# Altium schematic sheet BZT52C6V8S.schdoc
size 127 x 101 mm
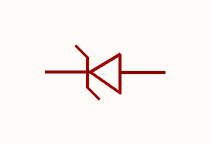
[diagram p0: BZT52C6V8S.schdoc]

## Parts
ZD?  bzt52c6v8s_c22613  [SOD-323_L1.8-W1.3-LS2.5-RD]  (value not drawn)

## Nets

Not connected (* = marked no-connect by the designer): ZD? 1(K) 2(A)

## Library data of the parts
ZD? = bzt52c6v8s_c22613: 二极管配置:1个独立式;稳压值(标称值):6.8V;稳压值(范围):6.4V~7.2V;耗散功率(Pd):200mW;; Manufacturer: CJ(江苏长电/长晶); AddInBom: yes; ModelId: db63db13d9e342eb939127d413d6200b; ModelTransform: 104.3305,51.181,0,0,0,0,0,-0.004,0; Diode Configuration: 1个独立式; Zener Voltage(Nom): 6.8V; Reverse Leakage Current (Ir): 2uA@4V; Pd - Power Dissipation: 200mW; Impedance(Zzt): 15Ω; Impedance(Zzk): 80Ω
